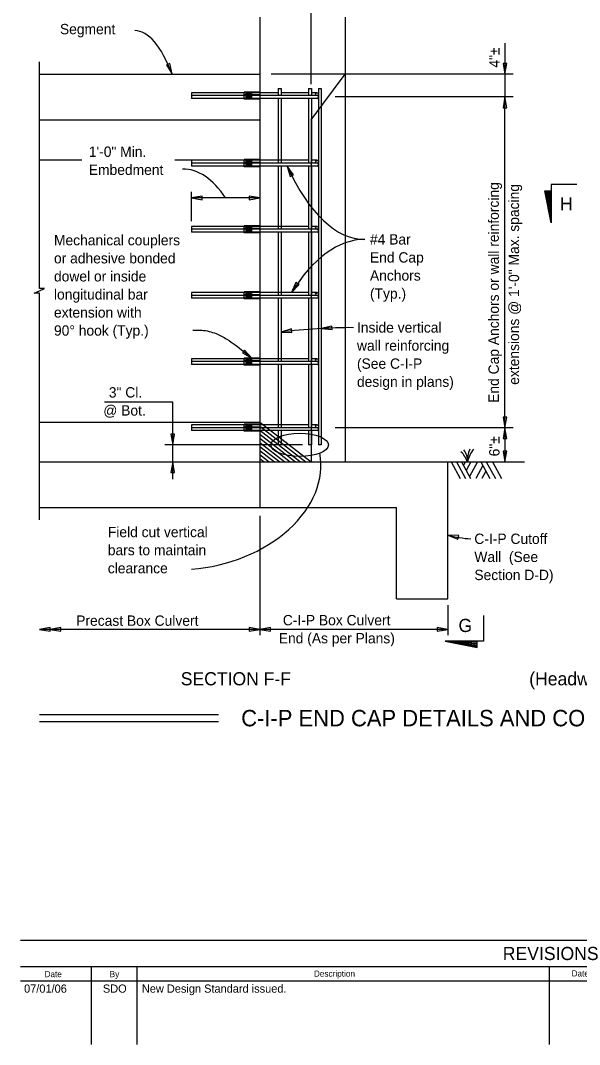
# Model space of a CAD drawing. Extents: x 10605.2 to 10672.7, y 76423.8 to 76450.2.
# Drawn here: x 10619.48 to 10627.65, y 76423.76 to 76438.73 of the extents above; entities that cross this region are included whole.
import ezdxf

# ---------------------------------------------------------------- set-up
doc = ezdxf.new("R2010")
doc.units = 0
for name, color, linetype in [('AdhocPoint_dp', 7, 'Continuous'), ('Border', 7, 'Continuous'), ('Patterning', 7, 'Continuous'), ('PlotBorder_dp', 7, 'Continuous'), ('SheetBorder_dp', 7, 'Continuous'), ('SheetLines_dp', 7, 'Continuous'), ('TextMisc', 7, 'Continuous')]:
    doc.layers.add(name, color=color, linetype=linetype)

msp = doc.modelspace()

# ---------------------------------------------------------------- linework, layer by layer
at = {"layer": 'AdhocPoint_dp'}
for p, q in [((10623.727, 76437.794), (10623.727, 76439.327)), ((10626.562, 76438.394), (10626.562, 76437.942)), ((10626.68, 76437.942), (10623.145, 76437.942)), ((10626.562, 76437.942), (10626.562, 76437.609)), ((10626.68, 76437.609), (10624.079, 76437.609)), ((10626.562, 76432.775), (10626.562, 76437.609)), ((10621.977, 76435.793), (10621.977, 76436.221)), ((10622.977, 76436.133), (10621.977, 76436.133)), ((10627.236, 76435.768), (10627.153, 76436.237)), ((10627.163, 76436.237), (10627.236, 76435.768)), ((10627.236, 76435.768), (10627.176, 76436.237)), ((10627.189, 76436.237), (10627.236, 76435.768)), ((10627.236, 76435.768), (10627.203, 76436.237)), ((10627.218, 76436.237), (10627.236, 76435.768)), ((10621.705, 76433.151), (10620.708, 76433.151)), ((10621.705, 76432.525), (10621.705, 76433.151)), ((10626.68, 76432.775), (10624.079, 76432.775)), ((10626.562, 76432.775), (10626.562, 76432.275)), ((10623.603, 76432.525), (10621.589, 76432.525)), ((10621.705, 76432.275), (10621.705, 76432.525)), ((10621.705, 76432.025), (10621.705, 76432.275)), ((10622.977, 76431.488), (10622.977, 76429.746)), ((10625.727, 76430.181), (10625.727, 76429.746)), ((10622.977, 76429.829), (10619.755, 76429.829)), ((10625.727, 76429.829), (10622.977, 76429.829)), ((10626.156, 76429.64), (10625.687, 76429.658)), ((10625.687, 76429.658), (10626.156, 76429.625)), ((10626.156, 76429.612), (10625.687, 76429.658)), ((10625.687, 76429.658), (10626.156, 76429.598)), ((10626.156, 76429.585), (10625.687, 76429.658)), ((10625.687, 76429.658), (10626.156, 76429.575)), ((10619.755, 76428.583), (10622.372, 76428.583)), ((10619.755, 76428.482), (10622.372, 76428.482))]:
    msp.add_line(p, q, dxfattribs=at)
for points in [[(10619.755, 76431.428), (10619.755, 76434.741), (10619.677, 76434.741), (10619.755, 76434.775), (10619.832, 76434.809), (10619.755, 76434.809), (10619.755, 76438.123)], [(10627.611, 76436.331), (10627.236, 76436.331), (10627.236, 76435.768), (10627.142, 76436.237), (10627.236, 76436.237)], [(10626.25, 76430.033), (10626.25, 76429.658), (10625.687, 76429.658), (10626.156, 76429.564), (10626.156, 76429.658)]]:
    msp.add_lwpolyline(points, dxfattribs=at)
for points in [[(10621.695, 76437.942), (10621.664, 76438.097), (10621.614, 76438.078)], [(10626.562, 76437.942), (10626.589, 76438.098), (10626.536, 76438.098)], [(10626.562, 76437.609), (10626.536, 76437.452), (10626.589, 76437.452)], [(10623.377, 76436.6), (10623.42, 76436.448), (10623.468, 76436.471)], [(10621.977, 76436.133), (10622.133, 76436.107), (10622.133, 76436.16)], [(10622.977, 76436.133), (10622.821, 76436.16), (10622.821, 76436.107)], [(10623.443, 76434.75), (10623.551, 76434.867), (10623.506, 76434.896)], [(10623.289, 76434.172), (10623.448, 76434.166), (10623.441, 76434.219)], [(10623.877, 76434.227), (10624.034, 76434.209), (10624.031, 76434.261)], [(10622.862, 76433.794), (10622.756, 76433.911), (10622.723, 76433.87)], [(10626.562, 76432.775), (10626.589, 76432.931), (10626.536, 76432.931)], [(10621.705, 76432.525), (10621.732, 76432.681), (10621.679, 76432.681)], [(10626.562, 76432.775), (10626.536, 76432.619), (10626.589, 76432.619)], [(10626.562, 76432.275), (10626.589, 76432.431), (10626.536, 76432.431)], [(10621.705, 76432.275), (10621.679, 76432.119), (10621.732, 76432.119)], [(10625.727, 76431.204), (10625.874, 76431.147), (10625.885, 76431.199)], [(10619.755, 76429.829), (10619.911, 76429.802), (10619.911, 76429.855)], [(10619.911, 76429.829), (10620.067, 76429.802), (10620.067, 76429.855)], [(10622.977, 76429.829), (10622.821, 76429.855), (10622.821, 76429.802)], [(10622.977, 76429.829), (10623.133, 76429.802), (10623.133, 76429.855)], [(10625.727, 76429.829), (10625.571, 76429.855), (10625.571, 76429.802)]]:
    msp.add_lwpolyline(points, close=True, dxfattribs=at)
for centre, radius, start, end in [((10624.304, 76426.434), 7.804, 89.6845, 97.4662), ((10626.203, 76433.121), 1.975, 256.0571, 265.9161)]:
    msp.add_arc(centre, radius, start, end, dxfattribs=at)
for centre, major_axis, ratio, start_param, end_param in [((10621.066, 76434.622), (-0.084, -3.958), 0.261149, 2.571065, 3.141593), ((10624.482, 76439.725), (-0.033, 4.197), 0.40152, 2.407456, 3.141215), ((10621.901, 76434.625), (0.052, -1.93), 0.503079, 2.454108, 3.141593), ((10624.541, 76431.628), (0.027, -3.9), 0.462577, 3.141946, 3.780946), ((10622.011, 76432.048), (-1.843, -0.35), 0.707446, 1.420997, 3.145082)]:
    msp.add_ellipse(centre, major_axis=major_axis, ratio=ratio, start_param=start_param, end_param=end_param, dxfattribs=at)
msp.add_ellipse((10623.562, 76432.525), major_axis=(0.421, 0), ratio=0.404515, dxfattribs=at)
msp.add_spline([(10621.999, 76434.201), (10622.128, 76434.201), (10622.339, 76434.151), (10622.496, 76434.069), (10622.62, 76433.985), (10622.862, 76433.794)], degree=3, dxfattribs=at)
at = {"layer": 'Border'}
for p, q in [((10634.938, 76425.284), (10619.479, 76425.284)), ((10634.938, 76424.898), (10619.479, 76424.898)), ((10620.512, 76424.898), (10620.512, 76423.762)), ((10621.181, 76424.898), (10621.181, 76423.762)), ((10627.209, 76424.898), (10627.209, 76423.762)), ((10619.479, 76424.693), (10634.938, 76424.693))]:
    msp.add_line(p, q, dxfattribs=at)
at = {"layer": 'Patterning'}
for p, q in [((10621.977, 76437.671), (10621.977, 76437.588)), ((10623.248, 76437.671), (10621.977, 76437.671)), ((10623.814, 76437.629), (10621.977, 76437.629)), ((10623.248, 76437.734), (10623.248, 76437.629)), ((10623.248, 76437.734), (10623.289, 76437.734)), ((10623.289, 76437.734), (10623.289, 76437.629)), ((10623.689, 76437.671), (10623.289, 76437.671)), ((10623.689, 76437.734), (10623.689, 76437.629)), ((10623.689, 76437.734), (10623.731, 76437.734)), ((10623.731, 76437.734), (10623.731, 76437.629)), ((10623.814, 76437.671), (10623.731, 76437.671)), ((10623.835, 76437.734), (10623.877, 76437.734)), ((10623.835, 76437.734), (10623.835, 76432.525)), ((10623.877, 76437.734), (10623.877, 76432.525)), ((10623.814, 76437.588), (10621.977, 76437.588)), ((10623.248, 76437.588), (10623.248, 76436.642)), ((10623.289, 76437.585), (10623.289, 76436.642)), ((10623.689, 76437.588), (10623.689, 76436.642)), ((10623.731, 76437.585), (10623.731, 76436.642)), ((10621.977, 76436.684), (10621.977, 76436.6)), ((10623.689, 76436.684), (10621.977, 76436.684)), ((10623.814, 76436.642), (10621.977, 76436.642)), ((10623.814, 76436.6), (10621.977, 76436.6)), ((10623.248, 76436.6), (10623.248, 76435.675)), ((10623.289, 76436.6), (10623.289, 76435.675)), ((10623.689, 76436.6), (10623.689, 76435.675)), ((10623.814, 76436.684), (10623.731, 76436.684)), ((10623.731, 76436.6), (10623.731, 76435.675)), ((10621.977, 76435.717), (10621.977, 76435.634)), ((10623.689, 76435.717), (10621.977, 76435.717)), ((10623.814, 76435.675), (10621.977, 76435.675)), ((10623.814, 76435.717), (10623.731, 76435.717)), ((10623.814, 76435.634), (10621.977, 76435.634)), ((10623.248, 76435.634), (10623.248, 76434.709)), ((10623.289, 76435.634), (10623.289, 76434.709)), ((10623.689, 76435.634), (10623.689, 76434.709)), ((10623.731, 76435.634), (10623.731, 76434.709)), ((10621.977, 76434.75), (10621.977, 76434.667)), ((10623.689, 76434.75), (10621.977, 76434.75)), ((10623.814, 76434.709), (10621.977, 76434.709)), ((10623.814, 76434.667), (10621.977, 76434.667)), ((10623.248, 76434.667), (10623.248, 76433.742)), ((10623.289, 76434.667), (10623.289, 76433.742)), ((10623.689, 76434.667), (10623.689, 76433.742)), ((10623.814, 76434.75), (10623.731, 76434.75)), ((10623.731, 76434.667), (10623.731, 76433.742)), ((10621.977, 76433.784), (10621.977, 76433.7)), ((10623.689, 76433.784), (10621.977, 76433.784)), ((10623.814, 76433.742), (10621.977, 76433.742)), ((10623.814, 76433.784), (10623.731, 76433.784)), ((10623.814, 76433.7), (10621.977, 76433.7)), ((10623.248, 76433.7), (10623.248, 76432.775)), ((10623.289, 76433.7), (10623.289, 76432.775)), ((10623.689, 76433.7), (10623.689, 76432.775)), ((10623.731, 76433.7), (10623.731, 76432.775)), ((10621.977, 76432.817), (10621.977, 76432.734)), ((10623.689, 76432.817), (10621.977, 76432.817)), ((10623.814, 76432.775), (10621.977, 76432.775)), ((10623.814, 76432.734), (10621.977, 76432.734)), ((10623.248, 76432.734), (10623.248, 76432.525)), ((10623.289, 76432.734), (10623.289, 76432.525)), ((10623.689, 76432.734), (10623.689, 76432.525)), ((10623.814, 76432.817), (10623.731, 76432.817)), ((10623.731, 76432.734), (10623.731, 76432.525)), ((10623.289, 76432.525), (10623.248, 76432.525)), ((10623.731, 76432.525), (10623.689, 76432.525)), ((10623.877, 76432.525), (10623.835, 76432.525))]:
    msp.add_line(p, q, dxfattribs=at)
for centre in [(10623.814, 76437.65), (10623.814, 76436.663), (10623.814, 76435.696), (10623.814, 76434.729), (10623.814, 76433.763), (10623.814, 76432.796)]:
    msp.add_circle(centre, 0.0208, dxfattribs=at)
for centre in [(10623.814, 76437.609), (10623.814, 76436.621), (10623.814, 76435.654), (10623.814, 76434.688), (10623.814, 76433.721), (10623.814, 76432.754)]:
    msp.add_arc(centre, 0.0208, 270, 90, dxfattribs=at)
at = {"layer": 'PlotBorder_dp'}
for p, q in [((10622.977, 76438.775), (10622.977, 76432.275)), ((10624.227, 76438.775), (10624.227, 76432.275)), ((10623.727, 76437.275), (10624.227, 76437.942)), ((10623.727, 76437.275), (10623.727, 76432.275)), ((10622.977, 76432.859), (10623.727, 76432.275)), ((10622.977, 76432.799), (10623.651, 76432.275)), ((10622.977, 76432.74), (10623.574, 76432.275)), ((10622.977, 76432.681), (10623.498, 76432.275)), ((10622.977, 76432.622), (10623.422, 76432.275)), ((10622.977, 76432.562), (10623.346, 76432.275)), ((10622.977, 76432.503), (10623.27, 76432.275)), ((10622.977, 76432.444), (10623.193, 76432.275)), ((10622.977, 76432.385), (10623.117, 76432.275)), ((10622.977, 76432.325), (10623.041, 76432.275)), ((10622.977, 76432.275), (10624.227, 76432.275))]:
    msp.add_line(p, q, dxfattribs=at)
at = {"layer": 'SheetLines_dp'}
for p, q in [((10622.977, 76437.681), (10622.747, 76437.681)), ((10622.977, 76437.64), (10622.747, 76437.64)), ((10622.82, 76437.671), (10622.78, 76437.671)), ((10622.78, 76437.64), (10622.78, 76437.671)), ((10622.82, 76437.629), (10622.78, 76437.629)), ((10622.78, 76437.588), (10622.78, 76437.629)), ((10622.82, 76437.629), (10622.78, 76437.629)), ((10622.79, 76437.64), (10622.79, 76437.671)), ((10622.79, 76437.588), (10622.79, 76437.629)), ((10622.8, 76437.64), (10622.8, 76437.671)), ((10622.8, 76437.588), (10622.8, 76437.629)), ((10622.81, 76437.64), (10622.81, 76437.671)), ((10622.81, 76437.588), (10622.81, 76437.629)), ((10622.86, 76437.671), (10622.82, 76437.671)), ((10622.82, 76437.64), (10622.82, 76437.671)), ((10622.86, 76437.629), (10622.82, 76437.629)), ((10622.82, 76437.588), (10622.82, 76437.629)), ((10622.86, 76437.629), (10622.82, 76437.629)), ((10622.83, 76437.64), (10622.83, 76437.671)), ((10622.83, 76437.588), (10622.83, 76437.629)), ((10622.84, 76437.64), (10622.84, 76437.671)), ((10622.84, 76437.588), (10622.84, 76437.629)), ((10622.85, 76437.64), (10622.85, 76437.671)), ((10622.85, 76437.588), (10622.85, 76437.629)), ((10622.86, 76437.64), (10622.86, 76437.671)), ((10622.86, 76437.588), (10622.86, 76437.629)), ((10622.977, 76437.578), (10622.747, 76437.578)), ((10622.82, 76437.588), (10622.78, 76437.588)), ((10622.86, 76437.588), (10622.82, 76437.588)), ((10622.977, 76436.694), (10622.747, 76436.694)), ((10622.977, 76436.652), (10622.747, 76436.652)), ((10622.977, 76436.59), (10622.747, 76436.59)), ((10622.82, 76436.684), (10622.78, 76436.684)), ((10622.78, 76436.652), (10622.78, 76436.684)), ((10622.82, 76436.642), (10622.78, 76436.642)), ((10622.78, 76436.6), (10622.78, 76436.642)), ((10622.82, 76436.642), (10622.78, 76436.642)), ((10622.82, 76436.6), (10622.78, 76436.6)), ((10622.79, 76436.652), (10622.79, 76436.684)), ((10622.79, 76436.6), (10622.79, 76436.642)), ((10622.8, 76436.652), (10622.8, 76436.684)), ((10622.8, 76436.6), (10622.8, 76436.642)), ((10622.81, 76436.652), (10622.81, 76436.684)), ((10622.81, 76436.6), (10622.81, 76436.642)), ((10622.86, 76436.684), (10622.82, 76436.684)), ((10622.82, 76436.652), (10622.82, 76436.684)), ((10622.86, 76436.642), (10622.82, 76436.642)), ((10622.82, 76436.6), (10622.82, 76436.642)), ((10622.86, 76436.642), (10622.82, 76436.642)), ((10622.86, 76436.6), (10622.82, 76436.6)), ((10622.83, 76436.652), (10622.83, 76436.684)), ((10622.83, 76436.6), (10622.83, 76436.642)), ((10622.84, 76436.652), (10622.84, 76436.684)), ((10622.84, 76436.6), (10622.84, 76436.642)), ((10622.85, 76436.652), (10622.85, 76436.684)), ((10622.85, 76436.6), (10622.85, 76436.642)), ((10622.86, 76436.652), (10622.86, 76436.684)), ((10622.86, 76436.6), (10622.86, 76436.642)), ((10622.977, 76435.727), (10622.747, 76435.727)), ((10622.977, 76435.686), (10622.747, 76435.686)), ((10622.82, 76435.717), (10622.78, 76435.717)), ((10622.78, 76435.686), (10622.78, 76435.717)), ((10622.82, 76435.675), (10622.78, 76435.675)), ((10622.78, 76435.634), (10622.78, 76435.675)), ((10622.82, 76435.675), (10622.78, 76435.675)), ((10622.79, 76435.686), (10622.79, 76435.717)), ((10622.79, 76435.634), (10622.79, 76435.675)), ((10622.8, 76435.686), (10622.8, 76435.717)), ((10622.8, 76435.634), (10622.8, 76435.675)), ((10622.81, 76435.686), (10622.81, 76435.717)), ((10622.81, 76435.634), (10622.81, 76435.675)), ((10622.86, 76435.717), (10622.82, 76435.717)), ((10622.82, 76435.686), (10622.82, 76435.717)), ((10622.86, 76435.675), (10622.82, 76435.675)), ((10622.82, 76435.634), (10622.82, 76435.675)), ((10622.86, 76435.675), (10622.82, 76435.675)), ((10622.83, 76435.686), (10622.83, 76435.717)), ((10622.83, 76435.634), (10622.83, 76435.675)), ((10622.84, 76435.686), (10622.84, 76435.717)), ((10622.84, 76435.634), (10622.84, 76435.675)), ((10622.85, 76435.686), (10622.85, 76435.717)), ((10622.85, 76435.634), (10622.85, 76435.675)), ((10622.86, 76435.686), (10622.86, 76435.717)), ((10622.86, 76435.634), (10622.86, 76435.675)), ((10622.977, 76435.623), (10622.747, 76435.623)), ((10622.82, 76435.634), (10622.78, 76435.634)), ((10622.86, 76435.634), (10622.82, 76435.634)), ((10622.977, 76434.76), (10622.747, 76434.76)), ((10622.977, 76434.719), (10622.747, 76434.719)), ((10622.977, 76434.657), (10622.747, 76434.657)), ((10622.82, 76434.75), (10622.78, 76434.75)), ((10622.78, 76434.719), (10622.78, 76434.75)), ((10622.82, 76434.709), (10622.78, 76434.709)), ((10622.78, 76434.667), (10622.78, 76434.709)), ((10622.82, 76434.709), (10622.78, 76434.709)), ((10622.82, 76434.667), (10622.78, 76434.667)), ((10622.79, 76434.719), (10622.79, 76434.75)), ((10622.79, 76434.667), (10622.79, 76434.709)), ((10622.8, 76434.719), (10622.8, 76434.75)), ((10622.8, 76434.667), (10622.8, 76434.709)), ((10622.81, 76434.719), (10622.81, 76434.75)), ((10622.81, 76434.667), (10622.81, 76434.709)), ((10622.86, 76434.75), (10622.82, 76434.75)), ((10622.82, 76434.719), (10622.82, 76434.75)), ((10622.86, 76434.709), (10622.82, 76434.709)), ((10622.82, 76434.667), (10622.82, 76434.709)), ((10622.86, 76434.709), (10622.82, 76434.709)), ((10622.86, 76434.667), (10622.82, 76434.667)), ((10622.83, 76434.719), (10622.83, 76434.75)), ((10622.83, 76434.667), (10622.83, 76434.709)), ((10622.84, 76434.719), (10622.84, 76434.75)), ((10622.84, 76434.667), (10622.84, 76434.709)), ((10622.85, 76434.719), (10622.85, 76434.75)), ((10622.85, 76434.667), (10622.85, 76434.709)), ((10622.86, 76434.719), (10622.86, 76434.75)), ((10622.86, 76434.667), (10622.86, 76434.709)), ((10622.977, 76433.794), (10622.747, 76433.794)), ((10622.977, 76433.752), (10622.747, 76433.752)), ((10622.82, 76433.784), (10622.78, 76433.784)), ((10622.78, 76433.752), (10622.78, 76433.784)), ((10622.82, 76433.742), (10622.78, 76433.742)), ((10622.78, 76433.7), (10622.78, 76433.742)), ((10622.82, 76433.742), (10622.78, 76433.742)), ((10622.79, 76433.752), (10622.79, 76433.784)), ((10622.79, 76433.7), (10622.79, 76433.742)), ((10622.8, 76433.752), (10622.8, 76433.784)), ((10622.8, 76433.7), (10622.8, 76433.742)), ((10622.81, 76433.752), (10622.81, 76433.784)), ((10622.81, 76433.7), (10622.81, 76433.742)), ((10622.86, 76433.784), (10622.82, 76433.784)), ((10622.82, 76433.752), (10622.82, 76433.784)), ((10622.86, 76433.742), (10622.82, 76433.742)), ((10622.82, 76433.7), (10622.82, 76433.742)), ((10622.86, 76433.742), (10622.82, 76433.742)), ((10622.83, 76433.752), (10622.83, 76433.784)), ((10622.83, 76433.7), (10622.83, 76433.742)), ((10622.84, 76433.752), (10622.84, 76433.784)), ((10622.84, 76433.7), (10622.84, 76433.742)), ((10622.85, 76433.752), (10622.85, 76433.784)), ((10622.85, 76433.7), (10622.85, 76433.742)), ((10622.86, 76433.752), (10622.86, 76433.784)), ((10622.86, 76433.7), (10622.86, 76433.742)), ((10622.977, 76433.69), (10622.747, 76433.69)), ((10622.82, 76433.7), (10622.78, 76433.7)), ((10622.86, 76433.7), (10622.82, 76433.7)), ((10622.977, 76432.827), (10622.747, 76432.827)), ((10622.977, 76432.786), (10622.747, 76432.786)), ((10622.977, 76432.723), (10622.747, 76432.723)), ((10622.82, 76432.817), (10622.78, 76432.817)), ((10622.78, 76432.786), (10622.78, 76432.817)), ((10622.82, 76432.775), (10622.78, 76432.775)), ((10622.78, 76432.734), (10622.78, 76432.775)), ((10622.82, 76432.775), (10622.78, 76432.775)), ((10622.82, 76432.734), (10622.78, 76432.734)), ((10622.79, 76432.786), (10622.79, 76432.817)), ((10622.79, 76432.734), (10622.79, 76432.775)), ((10622.8, 76432.786), (10622.8, 76432.817)), ((10622.8, 76432.734), (10622.8, 76432.775)), ((10622.81, 76432.786), (10622.81, 76432.817)), ((10622.81, 76432.734), (10622.81, 76432.775)), ((10622.86, 76432.817), (10622.82, 76432.817)), ((10622.82, 76432.786), (10622.82, 76432.817)), ((10622.86, 76432.775), (10622.82, 76432.775)), ((10622.82, 76432.734), (10622.82, 76432.775)), ((10622.86, 76432.775), (10622.82, 76432.775)), ((10622.86, 76432.734), (10622.82, 76432.734)), ((10622.83, 76432.786), (10622.83, 76432.817)), ((10622.83, 76432.734), (10622.83, 76432.775)), ((10622.84, 76432.786), (10622.84, 76432.817)), ((10622.84, 76432.734), (10622.84, 76432.775)), ((10622.85, 76432.786), (10622.85, 76432.817)), ((10622.85, 76432.734), (10622.85, 76432.775)), ((10622.86, 76432.786), (10622.86, 76432.817)), ((10622.86, 76432.734), (10622.86, 76432.775)), ((10625.727, 76432.275), (10626.846, 76432.275)), ((10625.776, 76432.275), (10625.907, 76432.036)), ((10625.854, 76432.275), (10625.985, 76432.036)), ((10625.928, 76432.275), (10626.059, 76432.036)), ((10625.982, 76432.275), (10625.955, 76432.225)), ((10626.063, 76432.275), (10625.995, 76432.152)), ((10626.162, 76432.275), (10626.045, 76432.061)), ((10626.207, 76432.275), (10626.338, 76432.036)), ((10626.289, 76432.275), (10626.421, 76432.036)), ((10626.378, 76432.275), (10626.509, 76432.036)), ((10626.236, 76432.222), (10626.134, 76432.036)), ((10626.28, 76432.142), (10626.222, 76432.036))]:
    msp.add_line(p, q, dxfattribs=at)
for points in [[(10622.747, 76437.64), (10622.747, 76437.681)], [(10622.747, 76437.578), (10622.747, 76437.64)], [(10622.747, 76436.652), (10622.747, 76436.694)], [(10622.747, 76436.59), (10622.747, 76436.652)], [(10622.747, 76435.686), (10622.747, 76435.727)], [(10622.747, 76435.623), (10622.747, 76435.686)], [(10622.747, 76434.719), (10622.747, 76434.76)], [(10622.747, 76434.657), (10622.747, 76434.719)], [(10622.747, 76433.752), (10622.747, 76433.794)], [(10622.747, 76433.69), (10622.747, 76433.752)], [(10622.747, 76432.786), (10622.747, 76432.827)], [(10622.747, 76432.723), (10622.747, 76432.786)]]:
    msp.add_lwpolyline(points, dxfattribs=at)
for centre, radius, start, end in [((10625.684, 76432.176), 0.342, 16.9178, 46.7762), ((10625.741, 76432.294), 0.272, 356.0505, 36.015), ((10626.415, 76432.296), 0.403, 155.9437, 182.9219), ((10626.576, 76432.124), 0.584, 144.3747, 165.0402)]:
    msp.add_arc(centre, radius, start, end, dxfattribs=at)
at = {"layer": 'TextMisc'}
for p, q in [((10619.755, 76437.942), (10622.977, 76437.942)), ((10619.755, 76437.275), (10622.977, 76437.275)), ((10619.755, 76436.692), (10620.378, 76436.692)), ((10621.738, 76436.692), (10622.977, 76436.692)), ((10619.755, 76432.859), (10622.977, 76432.859)), ((10619.755, 76432.275), (10622.977, 76432.275)), ((10622.977, 76432.275), (10622.977, 76431.609)), ((10624.227, 76432.275), (10625.727, 76432.275)), ((10625.727, 76430.275), (10625.727, 76432.275)), ((10619.755, 76431.609), (10624.977, 76431.609)), ((10624.977, 76430.275), (10624.977, 76431.609)), ((10624.977, 76430.275), (10625.727, 76430.275))]:
    msp.add_line(p, q, dxfattribs=at)

# ---------------------------------------------------------------- texts
at = {"layer": 'AdhocPoint_dp'}
for s, p in [('Segment', (10620.056, 76438.526)), ('1\'-0" Min.', (10620.478, 76436.734)), ('Embedment', (10620.478, 76436.47)), ('Mechanical couplers', (10619.969, 76435.441)), ('#4 Bar', (10624.588, 76435.453)), ('or adhesive bonded', (10619.969, 76435.177)), ('End Cap', (10624.588, 76435.189)), ('dowel or inside', (10619.969, 76434.913)), ('Anchors', (10624.588, 76434.925)), ('longitudinal bar', (10619.969, 76434.649)), ('(Typ.)', (10624.588, 76434.661)), ('extension with', (10619.969, 76434.385)), ('Inside vertical', (10624.398, 76434.165)), ('90° hook (Typ.)', (10619.969, 76434.121)), ('wall reinforcing', (10624.398, 76433.901)), ('(See C-I-P', (10624.398, 76433.637)), ('design in plans)', (10624.398, 76433.373)), ('3" Cl.', (10620.771, 76433.217)), ('@ Bot.', (10620.69, 76432.953)), ('Field cut vertical', (10620.756, 76431.176)), ('C-I-P Cutoff', (10626.114, 76431.077)), ('bars to maintain', (10620.756, 76430.912)), ('Wall  (See', (10626.114, 76430.813)), ('clearance', (10620.756, 76430.648)), ('Section D-D)', (10626.114, 76430.549)), ('C-I-P Box Culvert', (10623.314, 76429.888)), ('End (As per Plans)', (10623.255, 76429.624))]:
    msp.add_text(s, height=0.1512, dxfattribs=at).set_placement(p)
for s, p in [('End Cap Anchors or wall reinforcing', (10626.472, 76433.139)), ('extensions @ 1\'-0" Max. spacing', (10626.768, 76433.403))]:
    msp.add_text(s, height=0.1512, rotation=90, dxfattribs=at).set_placement(p)
at = {"layer": 'SheetBorder_dp'}
for s, height, rotation, p in [('4"±', 0.1512, 90, (10626.482, 76438.038)), ('6"±', 0.1512, 90, (10626.482, 76432.357)), ('Date', 0.0897, 359.8693, (10619.831, 76424.746)), ('Description', 0.09005, 0.0498, (10623.768, 76424.753)), ('Date', 0.0897, 359.8693, (10627.536, 76424.756))]:
    msp.add_text(s, height=height, rotation=rotation, dxfattribs=at).set_placement(p)
for s, height, p in [('H', 0.192, (10627.365, 76435.953)), ('Precast Box Culvert', 0.1512, (10620.294, 76429.881)), ('G', 0.192, (10625.882, 76429.79)), ('SECTION F-F', 0.192, (10621.822, 76429.011)), ('(Headwall, Toe Slab and Cutoff Wall Reinforcing not shown for clarity)', 0.192, (10626.916, 76429.011)), ('C-I-P END CAP DETAILS AND CONNECTION TO PRECAST BOX', 0.24, (10622.706, 76428.412)), ('REVISIONS', 0.1925, (10626.529, 76424.996)), ('By', 0.0901, (10620.783, 76424.746)), ('07/01/06', 0.12, (10619.532, 76424.519)), ('SDO', 0.12, (10620.684, 76424.519)), ('New Design Standard issued.', 0.12, (10621.254, 76424.519))]:
    msp.add_text(s, height=height, dxfattribs=at).set_placement(p)

doc.saveas('drawing.dxf')
